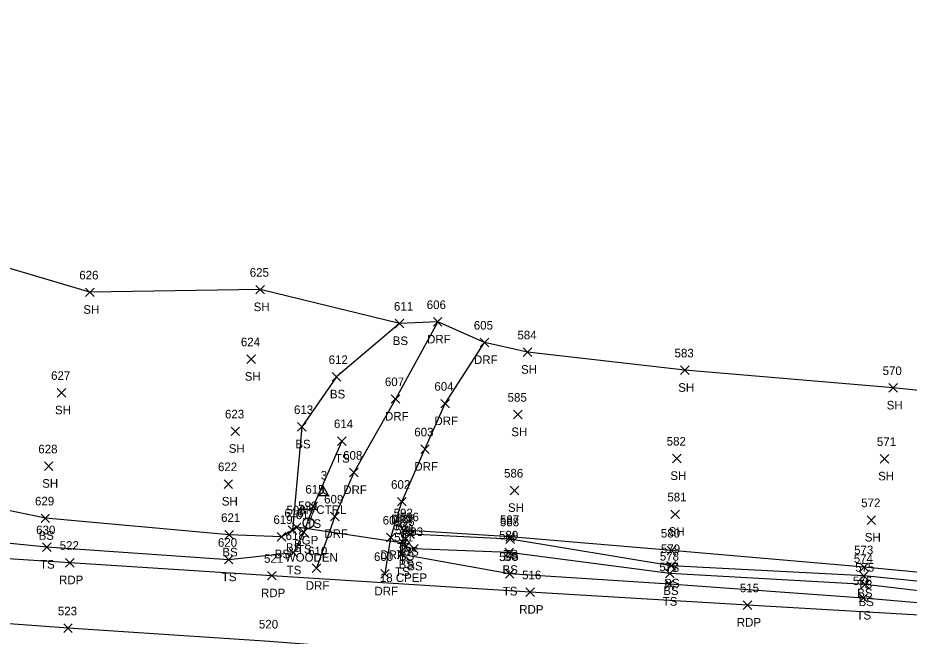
# Model space of a CAD drawing. Extents: x 1679360 to 1685861, y 903420 to 905946.
# Drawn here: x 1679882 to 1680089.3, y 904022.2 to 904166 of the extents above; entities that cross this region are included whole.
import ezdxf

# ---------------------------------------------------------------- set-up
doc = ezdxf.new("R2010")
doc.units = 0
for name, color, linetype in [('C_A', 7, 'Continuous'), ('C_I', 7, 'Continuous'), ('CPSM', 7, 'Continuous'), ('D_A', 7, 'Continuous'), ('D_C', 7, 'Continuous'), ('D_I', 7, 'Continuous'), ('D_TIC', 7, 'Continuous'), ('DCP', 7, 'Continuous'), ('L_A', 7, 'Continuous'), ('L_I', 7, 'Continuous'), ('L_TIC', 7, 'Continuous'), ('LELB', 7, 'Continuous'), ('LSOGP', 7, 'Continuous'), ('P_A', 7, 'Continuous'), ('P_I', 7, 'Continuous'), ('P_TIC', 7, 'Continuous'), ('PET', 7, 'Continuous'), ('PRC', 7, 'Continuous'), ('R_A', 7, 'Continuous'), ('R_C', 7, 'Continuous'), ('R_I', 7, 'Continuous'), ('R_TIC', 7, 'Continuous'), ('RDF', 7, 'Continuous'), ('RGP', 7, 'Continuous')]:
    doc.layers.add(name, color=color, linetype=linetype)

msp = doc.modelspace()

# ---------------------------------------------------------------- linework, layer by layer
at = {"layer": 'CPSM'}
for p, q in [((1679951.75, 904054.9), (1679953, 904057.07)), ((1679951.75, 904054.9), (1679953, 904055.62)), ((1679954.25, 904054.9), (1679953, 904057.07)), ((1679953, 904055.62), (1679953, 904057.07)), ((1679953, 904055.62), (1679953, 904055.62)), ((1679953, 904055.62), (1679954.25, 904054.9)), ((1679951.75, 904054.9), (1679954.25, 904054.9))]:
    msp.add_line(p, q, dxfattribs=at)
at = {"layer": 'D_TIC'}
for points in [[(1679945.84, 904046.51), (1679947.84, 904048.51)], [(1679947.84, 904046.51), (1679945.84, 904048.51)], [(1679970.72, 904042.79), (1679972.72, 904044.79)], [(1679972.72, 904042.79), (1679970.72, 904044.79)]]:
    msp.add_lwpolyline(points, dxfattribs=at)
at = {"layer": 'DCP'}
msp.add_lwpolyline([(1679971.72, 904043.79), (1679946.84, 904047.51)], dxfattribs=at)
at = {"layer": 'L_TIC'}
for points in [[(1679897.72, 904101.15), (1679899.72, 904103.15)], [(1679899.72, 904101.15), (1679897.72, 904103.15)], [(1679937.33, 904101.77), (1679939.33, 904103.77)], [(1679939.33, 904101.77), (1679937.33, 904103.77)], [(1679969.75, 904093.89), (1679971.75, 904095.89)], [(1679971.75, 904093.89), (1679969.75, 904095.89)], [(1679999.55, 904087.21), (1680001.55, 904089.21)], [(1680001.55, 904087.21), (1679999.55, 904089.21)], [(1679935.26, 904085.6), (1679937.26, 904087.6)], [(1679937.26, 904085.6), (1679935.26, 904087.6)], [(1680036.11, 904083.02), (1680038.11, 904085.02)], [(1680038.11, 904083.02), (1680036.11, 904085.02)], [(1679955.12, 904081.48), (1679957.12, 904083.48)], [(1679957.12, 904081.48), (1679955.12, 904083.48)], [(1680084.61, 904078.91), (1680086.61, 904080.91)], [(1680086.61, 904078.91), (1680084.61, 904080.91)], [(1679891.11, 904077.78), (1679893.11, 904079.78)], [(1679893.11, 904077.78), (1679891.11, 904079.78)], [(1679997.28, 904072.71), (1679999.28, 904074.71)], [(1679999.28, 904072.71), (1679997.28, 904074.71)], [(1679931.56, 904068.83), (1679933.56, 904070.83)], [(1679933.56, 904068.83), (1679931.56, 904070.83)], [(1679947.06, 904069.86), (1679949.06, 904071.86)], [(1679949.06, 904069.86), (1679947.06, 904071.86)], [(1679956.35, 904066.57), (1679958.35, 904068.57)], [(1679958.35, 904066.57), (1679956.35, 904068.57)], [(1680034.29, 904062.52), (1680036.29, 904064.52)], [(1680036.29, 904062.52), (1680034.29, 904064.52)], [(1680082.62, 904062.42), (1680084.62, 904064.42)], [(1680084.62, 904062.42), (1680082.62, 904064.42)], [(1679888.14, 904060.71), (1679890.14, 904062.71)], [(1679890.14, 904060.71), (1679888.14, 904062.71)], [(1679929.94, 904056.57), (1679931.94, 904058.57)], [(1679931.94, 904056.57), (1679929.94, 904058.57)], [(1679996.5, 904055.09), (1679998.5, 904057.09)], [(1679998.5, 904055.09), (1679996.5, 904057.09)], [(1679949.7, 904051.36), (1679951.7, 904053.36)], [(1679951.7, 904051.36), (1679949.7, 904053.36)], [(1680033.87, 904049.53), (1680035.87, 904051.53)], [(1680035.87, 904049.53), (1680033.87, 904051.53)], [(1679887.37, 904048.6), (1679889.37, 904050.6)], [(1679889.37, 904048.6), (1679887.37, 904050.6)], [(1680079.52, 904048.2), (1680081.52, 904050.2)], [(1680081.52, 904048.2), (1680079.52, 904050.2)], [(1679944.89, 904045.82), (1679946.89, 904047.82)], [(1679946.89, 904045.82), (1679944.89, 904047.82)], [(1679947.48, 904045.41), (1679949.48, 904047.41)], [(1679949.48, 904045.41), (1679947.48, 904047.41)], [(1679970.77, 904045.84), (1679972.77, 904047.84)], [(1679972.77, 904045.84), (1679970.77, 904047.84)], [(1679970.77, 904045.84), (1679972.77, 904047.84)], [(1679972.77, 904045.84), (1679970.77, 904047.84)], [(1679930.1, 904044.75), (1679932.1, 904046.75)], [(1679932.1, 904044.75), (1679930.1, 904046.75)], [(1679942.29, 904044.3), (1679944.29, 904046.3)], [(1679944.29, 904044.3), (1679942.29, 904046.3)], [(1679971.18, 904043.84), (1679973.18, 904045.84)], [(1679973.18, 904043.84), (1679971.18, 904045.84)], [(1679972.22, 904044.92), (1679974.22, 904046.92)], [(1679974.22, 904044.92), (1679972.22, 904046.92)], [(1679972.22, 904044.92), (1679974.22, 904046.92)], [(1679974.22, 904044.92), (1679972.22, 904046.92)], [(1679995.48, 904043.77), (1679997.48, 904045.77)], [(1679997.48, 904043.77), (1679995.48, 904045.77)], [(1679995.5, 904044.26), (1679997.5, 904046.26)], [(1679997.5, 904044.26), (1679995.5, 904046.26)], [(1679887.72, 904041.9), (1679889.72, 904043.9)], [(1679889.72, 904041.9), (1679887.72, 904043.9)], [(1679971.09, 904041.89), (1679973.09, 904043.89)], [(1679973.09, 904041.89), (1679971.09, 904043.89)], [(1679973.13, 904041.49), (1679975.13, 904043.49)], [(1679975.13, 904041.49), (1679973.13, 904043.49)], [(1680033.02, 904041.14), (1680035.02, 904043.14)], [(1680035.02, 904041.14), (1680033.02, 904043.14)], [(1679930.01, 904038.98), (1679932.01, 904040.98)], [(1679932.01, 904038.98), (1679930.01, 904040.98)], [(1679945.09, 904040.57), (1679947.09, 904042.57)], [(1679947.09, 904040.57), (1679945.09, 904042.57)], [(1679970.31, 904040.22), (1679972.31, 904042.22)], [(1679972.31, 904040.22), (1679970.31, 904042.22)], [(1679995.29, 904040.69), (1679997.29, 904042.69)], [(1679997.29, 904040.69), (1679995.29, 904042.69)], [(1680032.95, 904037.53), (1680034.95, 904039.53)], [(1680034.95, 904037.53), (1680032.95, 904039.53)], [(1680077.89, 904037.26), (1680079.89, 904039.26)], [(1680079.89, 904037.26), (1680077.89, 904039.26)], [(1679995.38, 904035.67), (1679997.38, 904037.67)], [(1679997.38, 904035.67), (1679995.38, 904037.67)], [(1680032.68, 904035.77), (1680034.68, 904037.77)], [(1680034.68, 904035.77), (1680032.68, 904037.77)], [(1680077.8, 904035.25), (1680079.8, 904037.25)], [(1680079.8, 904035.25), (1680077.8, 904037.25)], [(1680032.57, 904033.29), (1680034.57, 904035.29)], [(1680034.57, 904033.29), (1680032.57, 904035.29)], [(1680078.12, 904033.19), (1680080.12, 904035.19)], [(1680080.12, 904033.19), (1680078.12, 904035.19)], [(1680077.66, 904030.07), (1680079.66, 904032.07)], [(1680079.66, 904030.07), (1680077.66, 904032.07)]]:
    msp.add_lwpolyline(points, dxfattribs=at)
at = {"layer": 'LELB'}
for points in [[(1679957.35, 904067.57), (1679950.7, 904052.36), (1679948.48, 904046.41), (1679946.09, 904041.57), (1679931.01, 904039.98), (1679888.72, 904042.9), (1679856.91, 904046.05), (1679830.24, 904050.06), (1679823.69, 904055.74), (1679818.78, 904061.51), (1679813.5, 904065.59), (1679796.72, 904097.55), (1679771.59, 904129.9), (1679746.93, 904164.44), (1679719.12, 904199.21), (1679701.21, 904226.94), (1679680.19, 904259.65), (1679656.34, 904293.81), (1679636.23, 904329.88)], [(1679970.75, 904094.89), (1679956.12, 904082.48), (1679948.06, 904070.86), (1679945.89, 904046.82), (1679943.29, 904045.3), (1679931.1, 904045.75), (1679888.37, 904049.6), (1679852.38, 904057.08), (1679831.9, 904068.3), (1679818.58, 904068.02), (1679816.96, 904070.21), (1679822.07, 904077.46), (1679804.98, 904102.13), (1679779.08, 904133.42), (1679752.11, 904167.54), (1679728.27, 904203.83), (1679707.73, 904230.55), (1679684.13, 904262.03), (1679660.64, 904296.32), (1679637.49, 904331)], [(1680123.01, 904027.25), (1680078.66, 904031.07), (1680033.57, 904034.29), (1679996.38, 904036.67), (1679971.31, 904041.22), (1679971.77, 904046.84)], [(1680123.59, 904034.01), (1680078.89, 904038.26), (1680034.02, 904042.14), (1679996.5, 904045.26), (1679971.77, 904046.84)], [(1680123.08, 904029.02), (1680079.12, 904034.19), (1680033.68, 904036.77), (1679996.29, 904041.69), (1679974.13, 904042.49), (1679972.09, 904042.89), (1679972.18, 904044.84), (1679973.22, 904045.92)], [(1680123.39, 904031.76), (1680078.8, 904036.25), (1680033.95, 904038.53), (1679996.48, 904044.77), (1679973.22, 904045.92)]]:
    msp.add_lwpolyline(points, dxfattribs=at)
at = {"layer": 'LSOGP'}
msp.add_lwpolyline([(1680125.11, 904075.81), (1680085.61, 904079.91), (1680037.11, 904084.02), (1680000.55, 904088.21), (1679990.54, 904090.48), (1679979.64, 904095.26), (1679970.75, 904094.89), (1679938.33, 904102.77), (1679898.72, 904102.15), (1679863.8, 904112.52), (1679834.59, 904127.23), (1679795.98, 904142.46), (1679772.54, 904184.21)], dxfattribs=at)
at = {"layer": 'P_TIC'}
for points in [[(1679893.06, 904038.28), (1679895.06, 904040.28)], [(1679895.06, 904038.28), (1679893.06, 904040.28)], [(1679940.04, 904035.26), (1679942.04, 904037.26)], [(1679942.04, 904035.26), (1679940.04, 904037.26)], [(1680000.13, 904031.43), (1680002.13, 904033.43)], [(1680002.13, 904031.43), (1680000.13, 904033.43)], [(1680050.74, 904028.42), (1680052.74, 904030.42)], [(1680052.74, 904028.42), (1680050.74, 904030.42)], [(1679892.64, 904023.04), (1679894.64, 904025.04)], [(1679894.64, 904023.04), (1679892.64, 904025.04)]]:
    msp.add_lwpolyline(points, dxfattribs=at)
at = {"layer": 'PET'}
msp.add_lwpolyline([(1680210.84, 904017.73), (1680154.55, 904022.58), (1680102.27, 904026.43), (1680051.74, 904029.42), (1680001.13, 904032.43), (1679941.04, 904036.26), (1679894.06, 904039.28), (1679848.46, 904042.23), (1679824.08, 904043.91), (1679814.8, 904045.29), (1679808.83, 904044.91), (1679764.15, 904047.76), (1679716.13, 904050.9), (1679671, 904053.69), (1679626.09, 904056.57), (1679579.85, 904059.36), (1679535.31, 904061.44), (1679496.62, 904064.3), (1679468.44, 904066.43)], dxfattribs=at)
at = {"layer": 'PRC'}
msp.add_lwpolyline([(1680209.65, 904002.04), (1680152.97, 904005.78), (1680100.29, 904009.57), (1680049.21, 904012.91), (1679999.46, 904016.39), (1679940.5, 904020.99), (1679893.64, 904024.04), (1679847.03, 904027.44), (1679827.53, 904028.69), (1679808.61, 904029.86), (1679757.07, 904033.5), (1679707.39, 904036.98), (1679666.22, 904040.39), (1679623.03, 904043.25), (1679581.59, 904046.25), (1679534.87, 904049.67), (1679494.87, 904052.55), (1679467.34, 904054.68)], dxfattribs=at)
at = {"layer": 'R_TIC'}
for points in [[(1679978.64, 904094.26), (1679980.64, 904096.26)], [(1679980.64, 904094.26), (1679978.64, 904096.26)], [(1679989.54, 904089.48), (1679991.54, 904091.48)], [(1679991.54, 904089.48), (1679989.54, 904091.48)], [(1679968.85, 904076.34), (1679970.85, 904078.34)], [(1679970.85, 904076.34), (1679968.85, 904078.34)], [(1679980.36, 904075.26), (1679982.36, 904077.26)], [(1679982.36, 904075.26), (1679980.36, 904077.26)], [(1679975.69, 904064.66), (1679977.69, 904066.66)], [(1679977.69, 904064.66), (1679975.69, 904066.66)], [(1679959.13, 904059.24), (1679961.13, 904061.24)], [(1679961.13, 904059.24), (1679959.13, 904061.24)], [(1679970.28, 904052.47), (1679972.28, 904054.47)], [(1679972.28, 904052.47), (1679970.28, 904054.47)], [(1679954.73, 904049.04), (1679956.73, 904051.04)], [(1679956.73, 904049.04), (1679954.73, 904051.04)], [(1679967.77, 904044.14), (1679969.77, 904046.14)], [(1679969.77, 904044.14), (1679967.77, 904046.14)], [(1679950.43, 904036.98), (1679952.43, 904038.98)], [(1679952.43, 904036.98), (1679950.43, 904038.98)], [(1679966.39, 904035.69), (1679968.39, 904037.69)], [(1679968.39, 904035.69), (1679966.39, 904037.69)]]:
    msp.add_lwpolyline(points, dxfattribs=at)
at = {"layer": 'RDF'}
for points in [[(1679979.64, 904095.26), (1679969.85, 904077.34), (1679960.13, 904060.24), (1679955.73, 904050.04), (1679951.43, 904037.98)], [(1679967.39, 904036.69), (1679968.77, 904045.14), (1679971.28, 904053.47), (1679976.69, 904065.66), (1679981.36, 904076.26), (1679990.54, 904090.48)]]:
    msp.add_lwpolyline(points, dxfattribs=at)
at = {"layer": 'RGP'}
msp.add_line((1679949.56, 904048.52), (1679949.56, 904048.52), dxfattribs=at)
for radius in [1.25, 0.0833]:
    msp.add_circle((1679949.56, 904048.52), radius, dxfattribs=at)

# ---------------------------------------------------------------- texts
at = {"layer": 'C_A'}
msp.add_text('HVCTRL', height=2, dxfattribs=at).set_placement((1679947.69, 904050.62))
at = {"layer": 'C_I'}
msp.add_text('3', height=2, dxfattribs=at).set_placement((1679952.43, 904058.62))
at = {"layer": 'D_A'}
for p in [(1679946.22, 904042.51), (1679971.1, 904038.79)]:
    msp.add_text('P', height=2, dxfattribs=at).set_placement(p)
at = {"layer": 'D_C'}
msp.add_text('18 CPEP', height=2, dxfattribs=at).set_placement((1679966.19, 904034.79))
at = {"layer": 'D_I'}
for s, p in [('598', (1679944.48, 904050.51)), ('597', (1679969.36, 904046.79))]:
    msp.add_text(s, height=2, dxfattribs=at).set_placement(p)
at = {"layer": 'L_A'}
for s, p in [('SH', (1679897.21, 904097.15)), ('SH', (1679936.82, 904097.77)), ('BS', (1679969.19, 904089.89)), ('SH', (1679999.04, 904083.21)), ('SH', (1679934.75, 904081.6)), ('SH', (1680035.6, 904079.02)), ('BS', (1679954.56, 904077.48)), ('SH', (1680084.1, 904074.91)), ('SH', (1679890.6, 904073.78)), ('SH', (1679996.76, 904068.71)), ('BS', (1679946.51, 904065.86)), ('SH', (1679931.04, 904064.83)), ('TS', (1679955.76, 904062.57)), ('SH', (1680033.78, 904058.52)), ('SH', (1680082.1, 904058.42)), ('SH', (1679887.63, 904056.71)), ('SH', (1679929.42, 904052.57)), ('SH', (1679995.99, 904051.09)), ('TS', (1679949.11, 904047.36)), ('SH', (1680033.36, 904045.53)), ('BS', (1679886.81, 904044.6)), ('SH', (1680079.01, 904044.2)), ('BS', (1679944.33, 904041.82)), ('TS', (1679946.89, 904041.41)), ('TS', (1679970.18, 904041.84)), ('TS', (1679970.18, 904041.84)), ('BS', (1679971.66, 904040.92)), ('BS', (1679971.66, 904040.92)), ('BS', (1679929.54, 904040.75)), ('BS', (1679941.73, 904040.3)), ('BS', (1679970.62, 904039.84)), ('TS', (1679994.91, 904040.26)), ('BS', (1679994.93, 904039.77)), ('TS', (1679887.13, 904037.9)), ('BS', (1679970.54, 904037.89)), ('BS', (1679972.57, 904037.49)), ('BS', (1679994.73, 904036.69)), ('TS', (1680032.43, 904037.14)), ('TS', (1679929.42, 904034.98)), ('TS', (1679944.5, 904036.57)), ('TS', (1679969.72, 904036.22)), ('BS', (1680032.39, 904033.53)), ('TS', (1680077.29, 904033.26)), ('TS', (1679994.79, 904031.67)), ('BS', (1680032.12, 904031.77)), ('BS', (1680077.24, 904031.25)), ('TS', (1680031.98, 904029.29)), ('BS', (1680077.56, 904029.19)), ('TS', (1680077.07, 904026.07))]:
    msp.add_text(s, height=2, dxfattribs=at).set_placement(p)
at = {"layer": 'L_I'}
for s, p in [('626', (1679896.26, 904105.15)), ('625', (1679935.92, 904105.77)), ('611', (1679969.47, 904097.89)), ('584', (1679998.19, 904091.21)), ('624', (1679933.85, 904089.6)), ('583', (1680034.75, 904087.02)), ('612', (1679954.28, 904085.48)), ('570', (1680083.16, 904082.91)), ('627', (1679889.7, 904081.78)), ('585', (1679995.91, 904076.71)), ('623', (1679930.15, 904072.83)), ('613', (1679946.22, 904073.86)), ('614', (1679955.51, 904070.57)), ('582', (1680032.92, 904066.52)), ('571', (1680081.82, 904066.42)), ('628', (1679886.73, 904064.71)), ('622', (1679928.53, 904060.57)), ('586', (1679995.08, 904059.09)), ('615', (1679948.86, 904055.36)), ('581', (1680033.08, 904053.53)), ('629', (1679885.96, 904052.6)), ('572', (1680078.16, 904052.2)), ('616', (1679943.99, 904049.82)), ('617', (1679946.64, 904049.41)), ('592', (1679969.4, 904049.84)), ('592', (1679969.4, 904049.84)), ('621', (1679929.26, 904048.75)), ('619', (1679941.43, 904048.3)), ('595', (1679969.82, 904047.84)), ('596', (1679970.81, 904048.92)), ('596', (1679970.81, 904048.92)), ('588', (1679994.12, 904047.77)), ('587', (1679994.14, 904048.26)), ('630', (1679886.23, 904045.9)), ('594', (1679969.73, 904045.89)), ('593', (1679971.77, 904045.49)), ('580', (1680031.57, 904045.14)), ('620', (1679928.51, 904042.98)), ('618', (1679944.25, 904044.57)), ('591', (1679969.51, 904044.22)), ('589', (1679993.92, 904044.69)), ('579', (1680031.58, 904041.53)), ('573', (1680076.52, 904041.26)), ('590', (1679993.93, 904039.67)), ('578', (1680031.32, 904039.77)), ('574', (1680076.44, 904039.25)), ('577', (1680031.21, 904037.29)), ('575', (1680076.76, 904037.19)), ('576', (1680076.24, 904034.07))]:
    msp.add_text(s, height=2, dxfattribs=at).set_placement(p)
at = {"layer": 'P_A'}
for p in [(1679891.55, 904034.28), (1679938.53, 904031.26), (1679998.61, 904027.43), (1680049.23, 904024.42)]:
    msp.add_text('RDP', height=2, dxfattribs=at).set_placement(p)
at = {"layer": 'P_I'}
for s, p in [('522', (1679891.7, 904042.28)), ('521', (1679939.24, 904039.26)), ('516', (1679999.28, 904035.43)), ('515', (1680049.95, 904032.42)), ('523', (1679891.28, 904027.04)), ('520', (1679938.05, 904023.99))]:
    msp.add_text(s, height=2, dxfattribs=at).set_placement(p)
at = {"layer": 'R_A'}
for s, p in [('DRF', (1679977.18, 904090.26)), ('DRF', (1679988.08, 904085.48)), ('DRF', (1679967.38, 904072.34)), ('DRF', (1679978.89, 904071.26)), ('DRF', (1679974.22, 904060.66)), ('DRF', (1679957.67, 904055.24)), ('DRF', (1679968.82, 904048.47)), ('DRF', (1679953.26, 904045.04)), ('GP', (1679947.99, 904043.52)), ('DRF', (1679966.31, 904040.14)), ('DRF', (1679948.96, 904032.98)), ('DRF', (1679964.93, 904031.69))]:
    msp.add_text(s, height=2, dxfattribs=at).set_placement(p)
at = {"layer": 'R_C'}
msp.add_text('WOODEN', height=2, dxfattribs=at).set_placement((1679944.07, 904039.52))
at = {"layer": 'R_I'}
for s, p in [('606', (1679977.1, 904098.26)), ('605', (1679988.05, 904093.48)), ('607', (1679967.36, 904080.34)), ('604', (1679978.87, 904079.26)), ('603', (1679974.2, 904068.66)), ('608', (1679957.65, 904063.24)), ('602', (1679968.8, 904056.47)), ('599', (1679947.19, 904051.52)), ('609', (1679953.23, 904053.04)), ('601', (1679966.85, 904048.14)), ('610', (1679949.5, 904040.98)), ('600', (1679964.82, 904039.69))]:
    msp.add_text(s, height=2, dxfattribs=at).set_placement(p)

doc.saveas('drawing.dxf')
